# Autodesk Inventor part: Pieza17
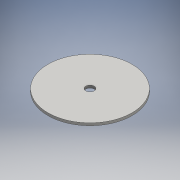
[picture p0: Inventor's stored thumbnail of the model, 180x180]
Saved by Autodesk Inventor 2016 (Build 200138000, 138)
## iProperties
Created: 2016-06
Part Number: Pieza17
Material: Genérico
Document SubType Name: Modeling
Designer: adm
Density: 1 g/cm^3
Appearance: Valor por defecto
Author: adm
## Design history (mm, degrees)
sketch "Boceto1"
  geometry: C1 r 50 at (0, 0); 1 further point
  constraints: 1 centre point, 1 coincident
  dimensions: "d0" = 100 diameter of C1
extrude "Extrusión1" new body sketch "Boceto1" distance "d1" = 3; taper "d2" = 0 deg
sketch "Boceto2"
  geometry: C1 r 5 at (0, 0); 1 further point
  constraints: 1 centre point, 1 coincident
  dimensions: "d3" = 10 diameter of C1
extrude "Extrusión2" cut sketch "Boceto2" distance "d4" = 3; taper "d5" = 0 deg
node "Sólido1"
